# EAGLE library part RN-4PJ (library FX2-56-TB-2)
Noch ein Widerstandsnetzwerk!
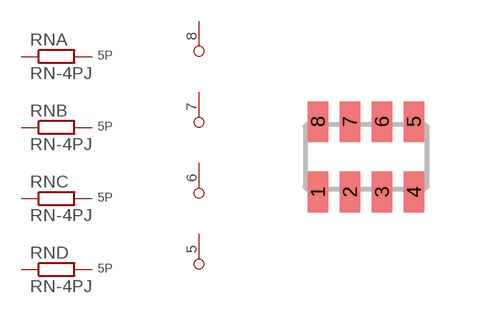
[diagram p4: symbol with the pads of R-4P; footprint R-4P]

Designator prefix RN; gates A=R-EU-EXTRA B=R-EU-EXTRA C=R-EU-EXTRA D=R-EU-EXTRA PA=PIN PB=PIN PC=PIN PD=PIN

## RN-4PJ  [R-4P]
1  A:1  pas
2  B:1  pas
3  C:1  pas
4  D:1  pas
5  PD:P$1  pas
6  PC:P$1  pas
7  PB:P$1  pas
8  PA:P$1  pas

## Footprint R-4P (pad centres in mm)
Widerstandsnetzwerk, 4 parallel, SMD 1206
smd 0.508 x 1.016: 1 -1.2,-0.88; 2 -0.4,-0.88; 3 0.4,-0.88; 4 1.2,-0.88; 5 1.2,0.88; 6 0.4,0.88; 7 -0.4,0.88; 8 -1.2,0.88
